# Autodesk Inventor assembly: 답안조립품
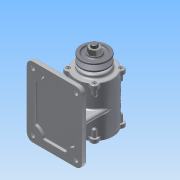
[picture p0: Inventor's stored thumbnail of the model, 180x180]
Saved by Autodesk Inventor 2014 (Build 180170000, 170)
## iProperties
Created: 2016-01
Part Number: 답안조립품
Document SubType Name: Assembly
Designer: Administrator
Author: Administrator
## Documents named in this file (12)
- C:\Users\Administrator\Desktop\460108V1019\답안조립품.iam
- C:\Users\Administrator\Desktop\460108V1019\V-벨트풀리.ipt
- C:\Users\Administrator\Desktop\460108V1019\너트 M12x1.25.ipt
- C:\Users\Administrator\Desktop\460108V1019\니플 M 6 x 0.75.ipt
- C:\Users\Administrator\Desktop\460108V1019\베어링 6204.ipt
- C:\Users\Administrator\Desktop\460108V1019\본체-1.ipt
- C:\Users\Administrator\Desktop\460108V1019\볼트 M4 x 12.ipt
- C:\Users\Administrator\Desktop\460108V1019\오일실.ipt
- C:\Users\Administrator\Desktop\460108V1019\축.ipt
- C:\Users\Administrator\Desktop\460108V1019\커버.ipt
- C:\Users\Administrator\Desktop\460108V1019\커버2.ipt
- C:\Users\Administrator\Desktop\460108V1019\키(4 x 4 x 12).ipt
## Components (6 placed, 5 different names)
1. V-벨트풀리:1
2. KS B 1012 클래스 1 일반 - 미터 M12x1.25:1
3. KS B 2023 6204 - 20 x 47 x 14:1
4. KS B 2804 D D - 20 32 8:1 — 플러쉬:1
5. KS B 1311 (I) 4 x 4 x 12:1
6. KS B 2023 6204 - 20 x 47 x 14:2
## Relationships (1: Flush 1)
- 플러쉬:1 [Flush]: KS B 2804 D D - 20 32 8:1
